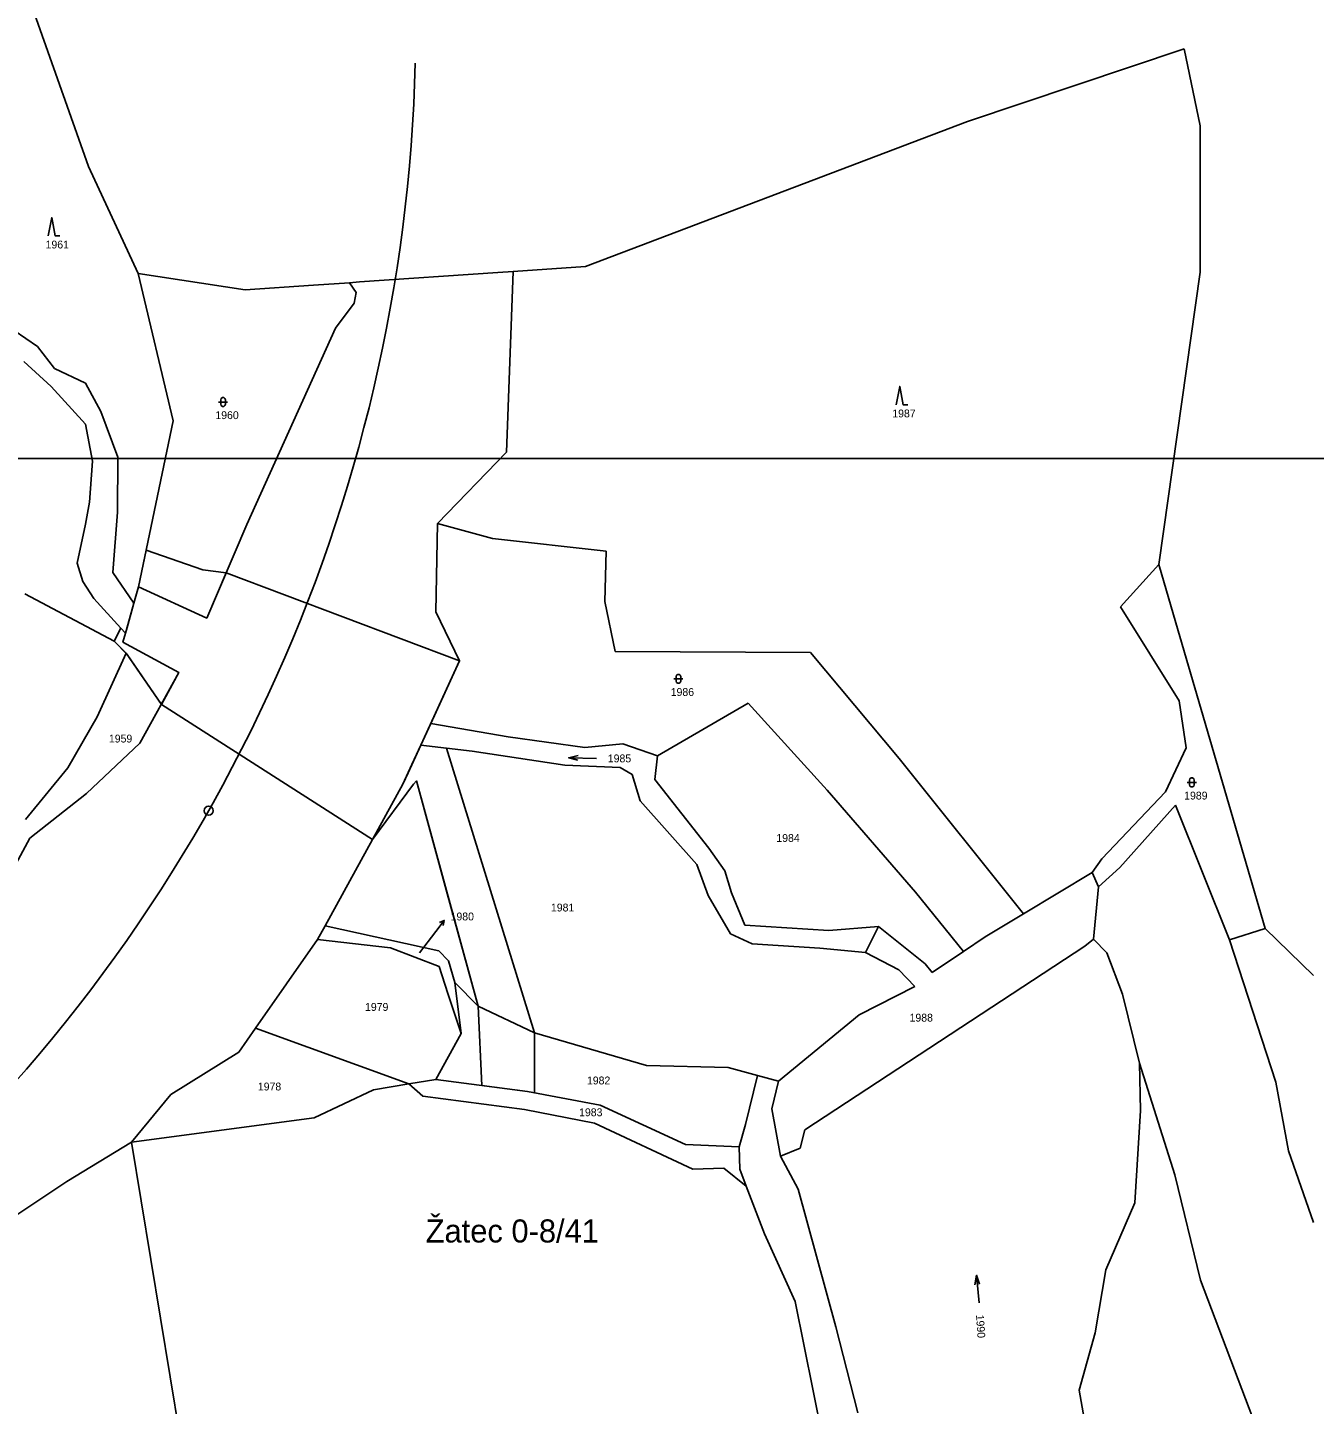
# Model space of a CAD drawing. Extents: x -801853 to -800578, y -1017479 to -1016338.
# Drawn here: x -801170.2 to -800891.5, y -1017204.8 to -1016906.7 of the extents above; entities that cross this region are included whole.
import ezdxf

# ---------------------------------------------------------------- set-up
doc = ezdxf.new("R2010")
doc.units = 0
for name, color, linetype in [('Default', 7, 'Continuous'), ('dočasné zábory', 7, 'Continuous'), ('KLADY_ZMVM', 7, 'Continuous'), ('KN_HRANICE', 7, 'Continuous'), ('KN_KULTURY', 7, 'Continuous'), ('KN_PARCELY', 7, 'Continuous'), ('obvod_stavby', 7, 'Continuous'), ('Svršek_hkm_100', 7, 'Continuous'), ('vlastníci', 7, 'Continuous'), ('Železniční svršek', 7, 'Continuous')]:
    doc.layers.add(name, color=color, linetype=linetype)

# ---------------------------------------------------------------- blocks, each defined once
blk = doc.blocks.new('308')
at = {"layer": 'Default'}
blk.add_lwpolyline([(-0.75, 0), (0, 4), (0.75, 0), (1.75, 0)], dxfattribs=at)
blk = doc.blocks.new('316')
at = {"layer": 'Default'}
for points in [[(-1, 1), (0.27, 1), (1, 1)], [(-0.5, 1.5), (-0.4, 1.79), (-0.15, 1.97), (0.16, 1.97), (0.41, 1.79), (0.51, 1.5), (0.51, 0.5), (0.41, 0.21), (0.16, 0.03), (-0.15, 0.03), (-0.4, 0.21), (-0.5, 0.5), (-0.5, 1.5)]]:
    blk.add_lwpolyline(points, dxfattribs=at)
blk = doc.blocks.new('802')
at = {"layer": 'Default'}
blk.add_line((-3, 0), (3, 0), dxfattribs=at)
blk.add_lwpolyline([(1, 0.5), (3, 0), (1, -0.5)], dxfattribs=at)
blk = doc.blocks.new('10292')
at = {"layer": 'Default'}
blk.add_line((0, 3), (0, 0), dxfattribs=at)
blk.add_lwpolyline([(-0.5, 2), (0, 3), (0.5, 2)], dxfattribs=at)

msp = doc.modelspace()

# ---------------------------------------------------------------- linework, layer by layer
at = {"layer": 'dočasné zábory'}
for points in [[(-801146.17, -1017027.77), (-801144.52, -1017019.83), (-801132.21, -1017024.12), (-801127.2, -1017024.74), (-801131.4, -1017034.56), (-801146.17, -1017027.77)], [(-801151.48, -1017039.58), (-801150, -1017036.76), (-801149.01, -1017037.86), (-801149.55, -1017039.8), (-801137.41, -1017046.38), (-801141.22, -1017053.25), (-801148.85, -1017042.19), (-801151.48, -1017039.58)], [(-801151.48, -1017039.58), (-801150, -1017036.76), (-801149.01, -1017037.86), (-801149.55, -1017039.8), (-801137.41, -1017046.38), (-801141.22, -1017053.25), (-801148.66, -1017042.44), (-801151.48, -1017039.58)], [(-801072.61, -1017118.61), (-801086, -1017069.82), (-801086.64, -1017070.52), (-801095.48, -1017082.49), (-801088.9, -1017070.5), (-801086.97, -1017066.29), (-801085.03, -1017062.08), (-801079.49, -1017062.75), (-801060.39, -1017124.37), (-801072.61, -1017118.61)], [(-801072.61, -1017118.61), (-801060.39, -1017124.37), (-801060.39, -1017137.35), (-801061.94, -1017137.05), (-801071.85, -1017135.76), (-801072.61, -1017118.61)]]:
    msp.add_lwpolyline(points, dxfattribs=at)
at = {"layer": 'KLADY_ZMVM'}
msp.add_line((-801848.02, -1017000), (-800625, -1017000), dxfattribs=at)
at = {"layer": 'KN_HRANICE'}
for p, q in [((-801173.56, -1016890), (-801157.02, -1016936.79)), ((-800966.67, -1016927.02), (-800919.72, -1016911.28)), ((-800919.72, -1016911.28), (-800916.22, -1016927.99)), ((-801049.4, -1016958.4), (-800966.67, -1016927.02)), ((-800916.22, -1016927.99), (-800916.27, -1016959.63)), ((-801157.02, -1016936.79), (-801146.24, -1016959.95)), ((-801098.33, -1016961.78), (-801068.35, -1016959.71)), ((-801068.35, -1016959.71), (-801065.05, -1016959.48)), ((-801066.45, -1016998.62), (-801065.05, -1016959.48)), ((-801065.05, -1016959.48), (-801049.4, -1016958.4)), ((-800916.27, -1016959.63), (-800925.21, -1017022.97)), ((-801138.7, -1016991.88), (-801146.24, -1016959.95)), ((-801146.24, -1016959.95), (-801123.1, -1016963.5)), ((-801123.1, -1016963.5), (-801108.28, -1016962.47)), ((-801108.28, -1016962.47), (-801100.45, -1016961.93)), ((-801100.45, -1016961.93), (-801098.33, -1016961.78)), ((-801099.01, -1016964.03), (-801100.45, -1016961.93)), ((-801099.44, -1016966.34), (-801099.01, -1016964.03)), ((-801103.54, -1016971.8), (-801099.44, -1016966.34)), ((-801168.07, -1016975.74), (-801173.07, -1016972.28)), ((-801122.73, -1017014.27), (-801103.54, -1016971.8)), ((-801164.36, -1016980.52), (-801168.07, -1016975.74)), ((-801165.08, -1016984.43), (-801171.01, -1016978.97)), ((-801157.66, -1016983.69), (-801164.36, -1016980.52)), ((-801154.36, -1016989.8), (-801157.66, -1016983.69)), ((-801157.69, -1016992.59), (-801165.08, -1016984.43)), ((-801156.11, -1017000.61), (-801157.69, -1016992.59)), ((-801150.62, -1016999.68), (-801154.36, -1016989.8)), ((-801146.17, -1017027.77), (-801138.7, -1016991.88)), ((-801156.79, -1017009.49), (-801156.11, -1017000.61)), ((-801150.74, -1017011.59), (-801150.62, -1016999.68)), ((-801081.43, -1017014.11), (-801066.45, -1016998.62)), ((-801156.79, -1017009.49), (-801157.64, -1017014.26)), ((-801151.72, -1017024.71), (-801150.74, -1017011.59)), ((-801159.44, -1017022.65), (-801157.64, -1017014.26)), ((-801131.4, -1017034.56), (-801122.73, -1017014.27)), ((-801081.81, -1017033.2), (-801081.43, -1017014.11)), ((-801081.43, -1017014.11), (-801069.54, -1017017.32)), ((-801069.54, -1017017.32), (-801044.91, -1017020.07)), ((-801044.91, -1017020.07), (-801045.15, -1017030.95)), ((-801159.44, -1017022.65), (-801158.23, -1017026.66)), ((-801147.17, -1017031.33), (-801151.72, -1017024.71)), ((-800933.53, -1017032.14), (-800925.21, -1017022.97)), ((-800925.21, -1017022.97), (-800922.04, -1017033.85)), ((-801158.23, -1017026.66), (-801155.85, -1017030.29)), ((-801147.17, -1017031.33), (-801146.17, -1017027.77)), ((-801146.17, -1017027.77), (-801131.4, -1017034.56)), ((-801170.76, -1017029.31), (-801151.48, -1017039.58)), ((-801150, -1017036.76), (-801155.85, -1017030.29)), ((-801148.65, -1017036.59), (-801147.17, -1017031.33)), ((-801045.15, -1017030.95), (-801042.92, -1017041.79)), ((-801076.63, -1017043.81), (-801081.81, -1017033.2)), ((-800920.82, -1017052.46), (-800933.53, -1017032.14)), ((-800922.04, -1017033.85), (-800902.21, -1017101.81)), ((-801150, -1017036.76), (-801151.48, -1017039.58)), ((-801150, -1017036.76), (-801149.01, -1017037.86)), ((-801149.01, -1017037.86), (-801148.65, -1017036.59)), ((-801151.48, -1017039.58), (-801148.85, -1017042.19)), ((-801149.55, -1017039.8), (-801149.01, -1017037.86)), ((-801137.41, -1017046.38), (-801149.55, -1017039.8)), ((-801155.16, -1017055.94), (-801148.85, -1017042.19)), ((-801042.92, -1017041.79), (-801000.61, -1017041.98)), ((-801000.61, -1017041.98), (-800981.44, -1017064.98)), ((-801082.88, -1017057.4), (-801076.63, -1017043.81)), ((-801145.88, -1017061.68), (-801137.41, -1017046.38)), ((-801014.12, -1017052.97), (-801033.76, -1017064.4)), ((-800997.04, -1017071.83), (-801014.12, -1017052.97)), ((-800919.32, -1017062.66), (-800920.82, -1017052.46)), ((-801161.48, -1017067), (-801155.16, -1017055.94)), ((-801082.88, -1017057.4), (-801085.03, -1017062.08)), ((-801066.15, -1017060.28), (-801082.88, -1017057.4)), ((-801049.51, -1017062.6), (-801066.15, -1017060.28)), ((-801157.42, -1017072.56), (-801145.88, -1017061.68)), ((-801088.9, -1017070.5), (-801085.03, -1017062.08)), ((-801085.03, -1017062.08), (-801073.95, -1017063.41)), ((-801073.95, -1017063.41), (-801053.83, -1017066.4)), ((-801041.29, -1017061.79), (-801049.51, -1017062.6)), ((-801033.76, -1017064.4), (-801041.29, -1017061.79)), ((-800923.75, -1017072.16), (-800919.32, -1017062.66)), ((-801170.68, -1017078.19), (-801161.48, -1017067)), ((-801053.83, -1017066.4), (-801041.9, -1017066.94)), ((-801041.9, -1017066.94), (-801039.25, -1017068.41)), ((-801033.76, -1017064.4), (-801034.38, -1017069.49)), ((-800981.44, -1017064.98), (-800954.55, -1017098.59)), ((-801039.25, -1017068.41), (-801037.51, -1017074.11)), ((-801034.38, -1017069.49), (-801022.63, -1017084.37)), ((-801169.74, -1017082.25), (-801157.42, -1017072.56)), ((-801105.75, -1017101.2), (-801088.9, -1017070.5)), ((-800977.94, -1017093.89), (-800997.04, -1017071.83)), ((-800937.55, -1017086.7), (-800923.75, -1017072.16)), ((-801037.51, -1017074.11), (-801025.28, -1017087.9)), ((-800933.62, -1017088.6), (-800921.62, -1017075.06)), ((-800921.62, -1017075.06), (-800909.89, -1017104.24)), ((-801179.48, -1017100.28), (-801169.74, -1017082.25)), ((-801022.63, -1017084.37), (-801019.21, -1017089.27)), ((-801025.28, -1017087.9), (-801022.81, -1017094.66)), ((-800939.68, -1017089.67), (-800937.55, -1017086.7)), ((-801019.21, -1017089.27), (-801017.73, -1017094.07)), ((-800954.55, -1017098.59), (-800939.68, -1017089.67)), ((-800939.68, -1017089.67), (-800938.24, -1017092.74)), ((-800938.24, -1017092.74), (-800933.62, -1017088.6)), ((-800967.52, -1017106.74), (-800977.94, -1017093.89)), ((-800938.24, -1017092.74), (-800939.36, -1017104.09)), ((-801022.81, -1017094.66), (-801017.99, -1017102.9)), ((-801017.73, -1017094.07), (-801014.89, -1017101.06)), ((-800962.84, -1017103.56), (-800954.55, -1017098.59)), ((-801107.38, -1017104.16), (-801105.75, -1017101.2)), ((-801081.11, -1017106.63), (-801105.75, -1017101.2)), ((-801017.99, -1017102.9), (-801013.25, -1017105.09)), ((-801014.89, -1017101.06), (-800996.7, -1017102.24)), ((-800996.7, -1017102.24), (-800985.89, -1017101.36)), ((-800988.75, -1017106.97), (-800985.89, -1017101.36)), ((-800985.89, -1017101.36), (-800975.8, -1017109.4)), ((-800909.89, -1017104.24), (-800902.21, -1017101.81)), ((-800902.21, -1017101.81), (-800891.71, -1017111.95)), ((-801107.38, -1017104.16), (-801120.85, -1017123.38)), ((-801091.59, -1017105.94), (-801107.38, -1017104.16)), ((-801013.25, -1017105.09), (-800998.64, -1017106.06)), ((-800941.26, -1017105.59), (-801001.86, -1017145.37)), ((-800967.52, -1017106.74), (-800962.84, -1017103.56)), ((-800939.36, -1017104.09), (-800941.26, -1017105.59)), ((-800936.45, -1017107.04), (-800939.36, -1017104.09)), ((-800909.89, -1017104.24), (-800899.86, -1017135.06)), ((-801081.08, -1017110), (-801091.59, -1017105.94)), ((-801079.03, -1017108.8), (-801081.11, -1017106.63)), ((-801077.69, -1017113.44), (-801079.03, -1017108.8)), ((-800998.64, -1017106.06), (-800988.75, -1017106.97)), ((-800988.75, -1017106.97), (-800981.55, -1017110.76)), ((-800974.27, -1017111.32), (-800967.52, -1017106.74)), ((-800933.11, -1017116.01), (-800936.45, -1017107.04)), ((-801079.17, -1017115.86), (-801081.08, -1017110)), ((-800981.55, -1017110.76), (-800978.03, -1017114.36)), ((-800975.8, -1017109.4), (-800974.27, -1017111.32)), ((-801076.29, -1017124.55), (-801077.69, -1017113.44)), ((-801072.61, -1017118.61), (-801077.69, -1017113.44)), ((-800978.03, -1017114.36), (-800990.08, -1017120.48)), ((-801076.29, -1017124.55), (-801079.17, -1017115.86)), ((-800929.36, -1017130.92), (-800933.11, -1017116.01)), ((-801060.39, -1017124.37), (-801072.61, -1017118.61)), ((-800990.08, -1017120.48), (-801007.59, -1017134.85)), ((-801120.85, -1017123.38), (-801124.46, -1017128.53)), ((-801120.85, -1017123.38), (-801087.64, -1017135.44)), ((-801081.77, -1017134.46), (-801076.29, -1017124.55)), ((-801036.16, -1017131.43), (-801060.39, -1017124.37)), ((-801124.46, -1017128.53), (-801139.16, -1017137.71)), ((-801018.45, -1017131.86), (-801036.16, -1017131.43)), ((-801012.13, -1017133.6), (-801018.45, -1017131.86)), ((-800921.75, -1017155.11), (-800929.36, -1017130.92)), ((-800929.15, -1017141.22), (-800929.36, -1017130.92)), ((-801095.3, -1017136.72), (-801087.64, -1017135.44)), ((-801087.64, -1017135.44), (-801081.77, -1017134.46)), ((-801087.64, -1017135.44), (-801084.58, -1017138.12)), ((-801081.77, -1017134.46), (-801061.94, -1017137.05)), ((-801014.73, -1017144.22), (-801012.13, -1017133.6)), ((-801007.59, -1017134.85), (-801012.13, -1017133.6)), ((-801009.05, -1017140.81), (-801007.59, -1017134.85)), ((-800899.86, -1017135.06), (-800897.14, -1017149.92)), ((-801139.16, -1017137.71), (-801147.67, -1017148.04)), ((-801095.3, -1017136.72), (-801108.14, -1017142.81)), ((-801084.58, -1017138.12), (-801062.58, -1017141)), ((-801061.94, -1017137.05), (-801046.19, -1017140.07)), ((-801062.58, -1017141), (-801047.43, -1017143.9)), ((-801046.19, -1017140.07), (-801027.73, -1017148.59)), ((-801007.17, -1017151.05), (-801009.05, -1017140.81)), ((-800930.37, -1017161.16), (-800929.15, -1017141.22)), ((-801108.14, -1017142.81), (-801147.67, -1017148.04)), ((-801047.43, -1017143.9), (-801026.14, -1017153.86)), ((-801014.73, -1017144.22), (-801016.11, -1017149.08)), ((-801001.86, -1017145.37), (-801002.87, -1017149.33)), ((-801147.67, -1017148.04), (-801161.67, -1017156.6)), ((-801147.67, -1017148.04), (-801120.7, -1017312.51)), ((-801027.73, -1017148.59), (-801016.11, -1017149.08)), ((-801016.11, -1017149.08), (-801015.97, -1017153.92)), ((-801002.87, -1017149.33), (-801007.17, -1017151.05)), ((-800897.14, -1017149.92), (-800891.71, -1017165.48)), ((-801007.17, -1017151.05), (-801003.34, -1017158.2)), ((-801161.67, -1017156.6), (-801192.33, -1017176.83)), ((-801026.14, -1017153.86), (-801019.43, -1017153.68)), ((-801019.43, -1017153.68), (-801014.57, -1017157.55)), ((-801015.97, -1017153.92), (-801014.57, -1017157.55)), ((-800916.2, -1017177.92), (-800921.75, -1017155.11)), ((-801014.57, -1017157.55), (-801010.59, -1017167.92)), ((-801003.34, -1017158.2), (-800995.15, -1017188.06)), ((-800936.68, -1017175.71), (-800930.37, -1017161.16)), ((-801010.59, -1017167.92), (-801003.97, -1017182.58)), ((-800939.01, -1017189.32), (-800936.68, -1017175.71)), ((-800904.03, -1017209.93), (-800916.2, -1017177.92)), ((-801003.97, -1017182.58), (-800982.5, -1017289.15)), ((-800995.15, -1017188.06), (-800990.37, -1017206.68)), ((-800942.43, -1017201.78), (-800939.01, -1017189.32)), ((-800938.06, -1017226.62), (-800942.43, -1017201.78))]:
    msp.add_line(p, q, dxfattribs=at)
at = {"layer": 'KN_PARCELY'}
msp.add_line((-801085.34, -1017107.05), (-801081.8, -1017102.41), dxfattribs=at)
at = {"layer": 'obvod_stavby'}
for points in [[(-801141.22, -1017053.25), (-801148.85, -1017042.19), (-801151.48, -1017039.58), (-801150, -1017036.76), (-801149.01, -1017037.86), (-801147.17, -1017031.33), (-801146.17, -1017027.77), (-801144.52, -1017019.83), (-801132.21, -1017024.12), (-801127.2, -1017024.74), (-801076.63, -1017043.81), (-801085.03, -1017062.08), (-801079.49, -1017062.75), (-801069.94, -1017093.56), (-801060.39, -1017124.37), (-801060.39, -1017137.35), (-801061.94, -1017137.05), (-801071.85, -1017135.76), (-801072.61, -1017118.61), (-801079.3, -1017094.22), (-801086, -1017069.82), (-801086.64, -1017070.52), (-801095.48, -1017082.49)], [(-801086, -1017069.82), (-801086.64, -1017070.52), (-801095.48, -1017082.49), (-801141.22, -1017053.25), (-801148.85, -1017042.19), (-801151.48, -1017039.58)]]:
    msp.add_lwpolyline(points, dxfattribs=at)
at = {"layer": 'Svršek_hkm_100'}
msp.add_circle((-801130.99, -1017076.27), 1, dxfattribs=at)
at = {"layer": 'vlastníci'}
for p, q in [((-801146.17, -1017027.77), (-801147.17, -1017031.33)), ((-801131.4, -1017034.56), (-801146.17, -1017027.77)), ((-801147.17, -1017031.33), (-801148.65, -1017036.59)), ((-801148.65, -1017036.59), (-801149.01, -1017037.86)), ((-801149.01, -1017037.86), (-801149.55, -1017039.8)), ((-801149.55, -1017039.8), (-801137.41, -1017046.38)), ((-801082.88, -1017057.4), (-801076.63, -1017043.81)), ((-801137.41, -1017046.38), (-801141.22, -1017053.25)), ((-801141.22, -1017053.25), (-801095.48, -1017082.49)), ((-801085.03, -1017062.08), (-801082.88, -1017057.4)), ((-801087.78, -1017068.07), (-801085.03, -1017062.08)), ((-801088.9, -1017070.5), (-801087.78, -1017068.07)), ((-801095.48, -1017082.49), (-801088.9, -1017070.5))]:
    msp.add_line(p, q, dxfattribs=at)
msp.add_lwpolyline([(-801076.63, -1017043.81), (-801127.2, -1017024.74), (-801131.4, -1017034.56)], dxfattribs=at)
at = {"layer": 'Železniční svršek'}
msp.add_arc((-801431.93, -1016905.94), 345.8, 311.7457, 358.6036, dxfattribs=at)

# ---------------------------------------------------------------- block references
at = {"layer": 'KN_KULTURY'}
for name, p in [('308', (-801164.97, -1016951.82)), ('308', (-800981.31, -1016988.4)), ('316', (-801127.87, -1016988.77)), ('316', (-801029.26, -1017048.72)), ('316', (-800918.06, -1017071.15))]:
    msp.add_blockref(name, p, dxfattribs=at)
for p, rotation in [((-801049.99, -1017064.88), 178.24716999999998), ((-800964.44, -1017179.86), 95.512064)]:
    msp.add_blockref('802', p, dxfattribs=dict(at, rotation=rotation))
at = {"layer": 'KN_PARCELY', "rotation": -37.367466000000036}
msp.add_blockref('10292', (-801081.8, -1017102.41), dxfattribs=at)

# ---------------------------------------------------------------- texts
at = {"layer": 'KLADY_ZMVM'}
msp.add_text('Žatec 0-8/41', height=5, dxfattribs=at).set_placement((-801083.99, -1017169.78))
at = {"layer": 'KN_PARCELY'}
for s, height, p in [('1961', 1.7, (-801166.3, -1016954.52)), ('1987', 1.7, (-800982.93, -1016991.1)), ('1960', 1.7, (-801129.53, -1016991.47)), ('1986', 1.7, (-801030.92, -1017051.42)), ('1959', 1.7, (-801152.59, -1017061.5)), ('1985', 1.7, (-801044.54, -1017065.8)), ('1989', 1.7, (-800919.72, -1017073.85)), ('1984', 1.7, (-801008.04, -1017083.03)), ('1981', 1.7, (-801056.86, -1017098.09)), ('1980', 1.7, (-801078.59, -1017100.03)), ('1980', 0.1, (-801085.32, -1017107.05)), ('1979', 1.7, (-801097.12, -1017119.62)), ('1988', 1.7, (-800979.19, -1017121.94)), ('1978', 1.7, (-801120.33, -1017136.85)), ('1982', 1.7, (-801049.06, -1017135.54)), ('1983', 1.7, (-801050.76, -1017142.43))]:
    msp.add_text(s, height=height, dxfattribs=at).set_placement(p)
msp.add_text('1990', height=1.7, rotation=273.759, dxfattribs=at).set_placement((-800964.8, -1017185.47))

doc.saveas('drawing.dxf')
